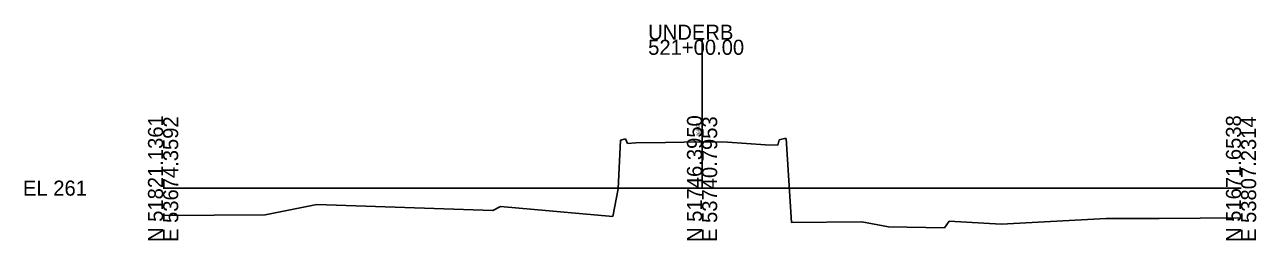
# Model space of a CAD drawing. Extents: x 12366 to 12594, y 96215 to 101752.
# Drawn here: x 12365.6 to 12594.1, y 99714.9 to 99755 of the extents above; entities that cross this region are included whole.
import ezdxf

# ---------------------------------------------------------------- set-up
doc = ezdxf.new("R2010")
doc.units = 0
for name, color, linetype in [('Level 10', 7, 'Continuous'), ('Level 60', 7, 'Continuous'), ('Level 63', 7, 'Continuous')]:
    doc.layers.add(name, color=color, linetype=linetype)

msp = doc.modelspace()

# ---------------------------------------------------------------- linework, layer by layer
at = {"layer": 'Level 60'}
for p, q in [((12475.72, 99724.52), (12476.15, 99733.55)), ((12476.15, 99733.55), (12477.11, 99733.8)), ((12477.11, 99733.8), (12477.49, 99732.92)), ((12477.49, 99732.92), (12479.03, 99733.02)), ((12479.03, 99733.02), (12484.5, 99733.12)), ((12484.5, 99733.12), (12491.3, 99733.25)), ((12491.3, 99733.25), (12496.05, 99733.18)), ((12496.05, 99733.18), (12503.04, 99732.7)), ((12503.04, 99732.7), (12505.35, 99732.61)), ((12505.35, 99732.61), (12505.62, 99733.62)), ((12505.62, 99733.62), (12506.61, 99733.82)), ((12506.61, 99733.82), (12506.91, 99733.82)), ((12506.91, 99733.82), (12507.9, 99718.29)), ((12474.73, 99719.36), (12475.72, 99724.52)), ((12410.23, 99719.66), (12419.82, 99721.59)), ((12419.82, 99721.59), (12452.51, 99720.51)), ((12452.51, 99720.51), (12453.92, 99721.21)), ((12453.92, 99721.21), (12474.73, 99719.36)), ((12391.3, 99719.55), (12410.23, 99719.66)), ((12507.9, 99718.29), (12520.92, 99718.37)), ((12520.92, 99718.37), (12525.91, 99717.48)), ((12536.3, 99717.28), (12537.12, 99718.51)), ((12537.12, 99718.51), (12546.79, 99717.95)), ((12546.79, 99717.95), (12566.3, 99719.02)), ((12566.3, 99719.02), (12567.11, 99719.02)), ((12567.11, 99719.02), (12576.11, 99719)), ((12576.11, 99719), (12591.3, 99719.14)), ((12525.91, 99717.48), (12536.3, 99717.28))]:
    msp.add_line(p, q, dxfattribs=at)
at = {"layer": 'Level 63'}
for p, q in [((12491.3, 99724.64), (12491.3, 99752.18)), ((12391.3, 99724.64), (12491.3, 99724.64)), ((12491.3, 99724.64), (12591.3, 99724.64))]:
    msp.add_line(p, q, dxfattribs=at)

# ---------------------------------------------------------------- texts
at = {"layer": 'Level 10'}
msp.add_text('269.62', height=0.6, rotation=90, dxfattribs=at).set_placement((12490.9, 99734.25))
at = {"layer": 'Level 63'}
for s, p in [('UNDERB', (12481.3, 99752.18)), ('521+00.00', (12481.3, 99749.38)), ('EL 261', (12365.3, 99723.24))]:
    msp.add_text(s, height=2.8, dxfattribs=at).set_placement(p)
for s, p in [('N 51821.1361', (12391.3, 99714.64)), ('E 53674.3592', (12394.1, 99714.64)), ('N 51746.3950', (12491.3, 99714.64)), ('E 53740.7953', (12494.1, 99714.64)), ('N 51671.6538', (12591.3, 99714.64)), ('E 53807.2314', (12594.1, 99714.64))]:
    msp.add_text(s, height=2.8, rotation=90, dxfattribs=at).set_placement(p)

doc.saveas('drawing.dxf')
